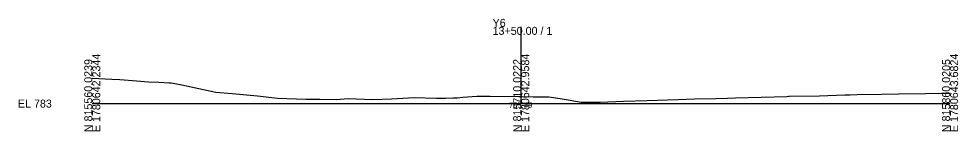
# Model space of a CAD drawing. Extents: x -26 to 1603, y -10 to 6024.
# Drawn here: x -25.7 to 302.8, y 4990.3 to 5029.7 of the extents above; entities that cross this region are included whole.
import ezdxf

# ---------------------------------------------------------------- set-up
doc = ezdxf.new("R2010")
doc.units = 0
for name, color, linetype in [('Exist Cross Section Cell', 7, 'Continuous'), ('Exist XS Center Line Elevation Label', 7, 'Continuous'), ('Exist XS Ground Line', 7, 'Continuous')]:
    doc.layers.add(name, color=color, linetype=linetype)

msp = doc.modelspace()

# ---------------------------------------------------------------- linework, layer by layer
at = {"layer": 'Exist Cross Section Cell'}
for p, q in [((150, 5000), (150, 5026.89)), ((0, 5000), (150, 5000)), ((150, 5000), (300, 5000))]:
    msp.add_line(p, q, dxfattribs=at)
at = {"layer": 'Exist XS Ground Line'}
for p, q in [((0, 5008.96), (6.79, 5008.61)), ((6.79, 5008.61), (9.59, 5008.43)), ((9.59, 5008.43), (11.12, 5008.32)), ((11.12, 5008.32), (14.02, 5008.09)), ((14.02, 5008.09), (19.71, 5007.67)), ((19.71, 5007.67), (23.27, 5007.47)), ((23.27, 5007.47), (26.89, 5007.32)), ((26.89, 5007.32), (27.54, 5007.3)), ((27.54, 5007.3), (28.28, 5007.14)), ((28.28, 5007.14), (28.9, 5007.03)), ((28.9, 5007.03), (31.27, 5006.57)), ((31.27, 5006.57), (43.24, 5004.03)), ((43.24, 5004.03), (48.9, 5003.53)), ((291.41, 5003.52), (297.02, 5003.64)), ((297.02, 5003.64), (300, 5003.63)), ((48.9, 5003.53), (57.79, 5002.73)), ((57.79, 5002.73), (64.81, 5001.86)), ((64.81, 5001.86), (74.66, 5001.53)), ((74.66, 5001.53), (76.04, 5001.52)), ((76.04, 5001.52), (77.43, 5001.54)), ((77.43, 5001.54), (79.62, 5001.51)), ((79.62, 5001.51), (85.28, 5001.43)), ((85.28, 5001.43), (89.46, 5001.82)), ((89.46, 5001.82), (98.03, 5001.47)), ((98.03, 5001.47), (104.69, 5001.72)), ((104.69, 5001.72), (112.55, 5002.13)), ((112.55, 5002.13), (120.33, 5001.92)), ((120.33, 5001.92), (123.51, 5001.91)), ((123.51, 5001.91), (126.26, 5001.98)), ((126.26, 5001.98), (127.56, 5001.98)), ((127.56, 5001.98), (129.62, 5002.2)), ((129.62, 5002.2), (134.51, 5002.62)), ((134.51, 5002.62), (137.82, 5002.58)), ((137.82, 5002.58), (138.41, 5002.56)), ((138.41, 5002.56), (139.11, 5002.56)), ((139.11, 5002.56), (149.2, 5002.5)), ((149.2, 5002.5), (150, 5002.49)), ((150, 5002.49), (154.16, 5002.41)), ((154.16, 5002.41), (159.72, 5002.36)), ((159.72, 5002.36), (163.61, 5001.76)), ((163.61, 5001.76), (166.39, 5001.37)), ((166.39, 5001.37), (171.02, 5000.51)), ((171.02, 5000.51), (171.45, 5000.53)), ((171.45, 5000.53), (177.63, 5000.52)), ((177.63, 5000.52), (185.75, 5000.84)), ((185.75, 5000.84), (194.06, 5001.13)), ((194.06, 5001.13), (204.76, 5001.43)), ((204.76, 5001.43), (210.59, 5001.64)), ((210.59, 5001.64), (218.04, 5001.81)), ((218.04, 5001.81), (222.1, 5001.92)), ((222.1, 5001.92), (224.96, 5002)), ((224.96, 5002), (242.93, 5002.53)), ((242.93, 5002.53), (243.46, 5002.55)), ((243.46, 5002.55), (243.88, 5002.56)), ((243.88, 5002.56), (254.31, 5002.76)), ((254.31, 5002.76), (263.24, 5003.07)), ((263.24, 5003.07), (265.01, 5003.12)), ((265.01, 5003.12), (267.52, 5003.16)), ((267.52, 5003.16), (276.12, 5003.34)), ((276.12, 5003.34), (282.01, 5003.36)), ((282.01, 5003.36), (291.41, 5003.52))]:
    msp.add_line(p, q, dxfattribs=at)

# ---------------------------------------------------------------- texts
at = {"layer": 'Exist Cross Section Cell'}
for s, p in [('Y6', (140, 5026.89)), ('13+50.00 / 1', (140, 5024.09)), ('EL 783', (-26, 4998.6))]:
    msp.add_text(s, height=2.8, dxfattribs=at).set_placement(p)
for s, p in [('E 1780642.2344', (2.8, 4990)), ('E 1780642.9584', (152.8, 4990)), ('E 1780643.6824', (302.8, 4990)), ('N 815560.0239', (0, 4990)), ('N 815710.0222', (150, 4990)), ('N 815860.0205', (300, 4990))]:
    msp.add_text(s, height=2.8, rotation=90, dxfattribs=at).set_placement(p)
at = {"layer": 'Exist XS Center Line Elevation Label'}
msp.add_text('785.49', height=2, dxfattribs=at).set_placement((145.73, 4998.49))

doc.saveas('drawing.dxf')
